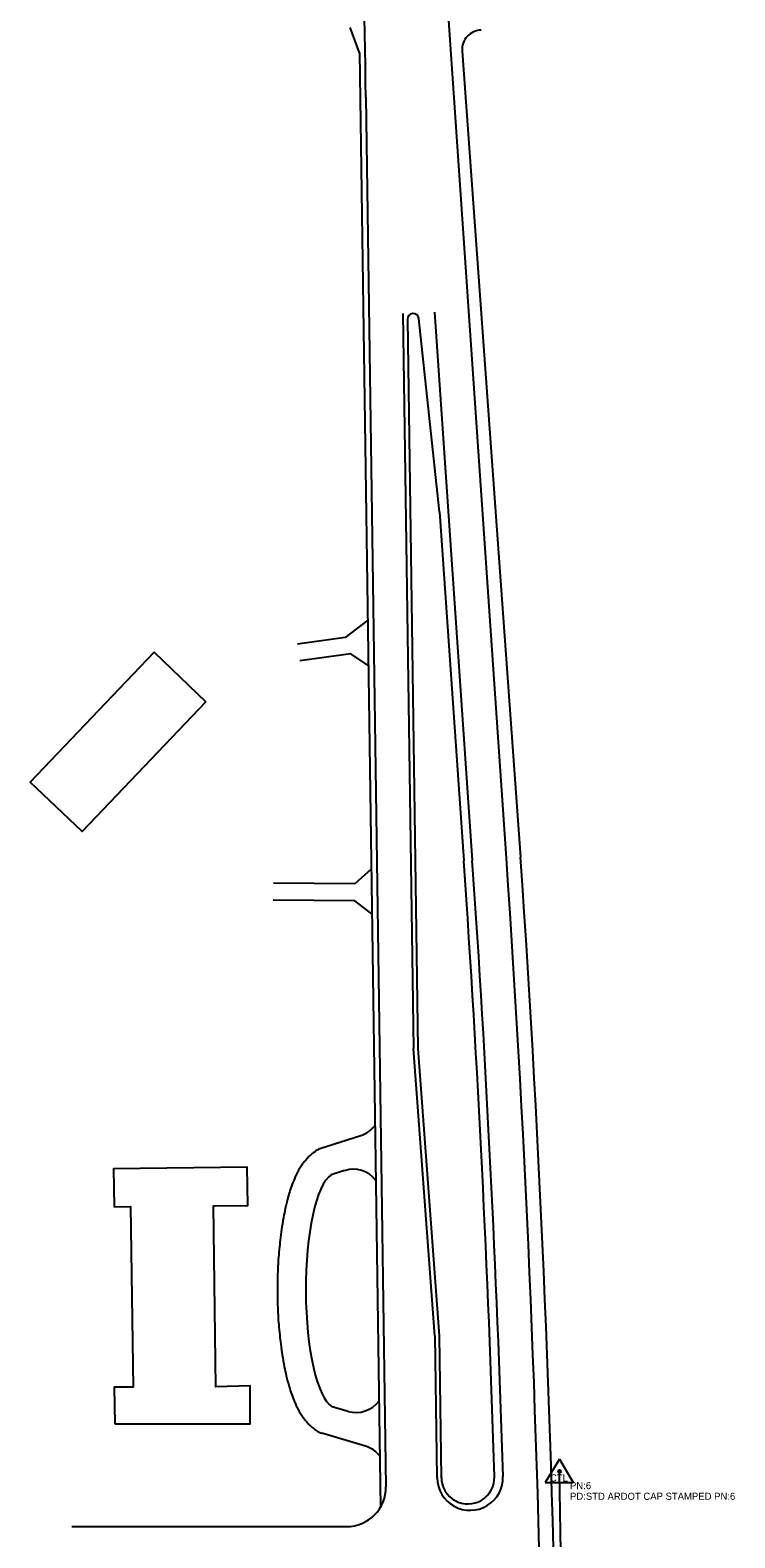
# Model space of a CAD drawing. Extents: x 1676038 to 1677961, y 226475 to 233854.
# Drawn here: x 1677093 to 1677589, y 230414 to 231476 of the extents above; entities that cross this region are included whole.
import ezdxf

# ---------------------------------------------------------------- set-up
doc = ezdxf.new("R2010")
doc.units = 0
for name, color, linetype in [('S_BASELINE', 7, 'Continuous'), ('S_BUILDING', 7, 'Continuous'), ('S_DRIVEWAY', 7, 'Continuous'), ('S_EDGE_PAVEMENT', 7, 'Continuous'), ('S_PRIMARY_CTL', 7, 'Continuous'), ('S_PRIMARY_CTL_ANNOT', 7, 'Continuous'), ('S_SHOULDER', 7, 'Continuous')]:
    doc.layers.add(name, color=color, linetype=linetype)

msp = doc.modelspace()

# ---------------------------------------------------------------- linework, layer by layer
at = {"layer": 'S_BASELINE'}
msp.add_line((1677475.6, 229873.4), (1677466, 230460.5), dxfattribs=at)
at = {"layer": 'S_BUILDING'}
for points in [[(1677217.2, 231002.7), (1677130, 230911.2), (1677093.5, 230946), (1677180.8, 231037.6)], [(1677153.1, 230494.1), (1677248.4, 230494), (1677248.4, 230520.8), (1677224.2, 230520.2), (1677222.5, 230647.6), (1677246.6, 230647.9), (1677246.2, 230674.8), (1677152.2, 230673.6), (1677152.6, 230646.8), (1677164.2, 230647), (1677165.9, 230519.9), (1677152.5, 230519.8)]]:
    msp.add_lwpolyline(points, close=True, dxfattribs=at)
at = {"layer": 'S_DRIVEWAY'}
for p, q in [((1677331.1, 231060.1), (1677315.3, 231048)), ((1677315.3, 231048), (1677281.7, 231043.3)), ((1677319.2, 231036.4), (1677283.3, 231031.4)), ((1677331.5, 231028.1), (1677319.2, 231036.4)), ((1677333.6, 230884.8), (1677322.1, 230874.5)), ((1677322.1, 230874.5), (1677264.7, 230874.8)), ((1677321.9, 230862.5), (1677264.6, 230862.8)), ((1677334.1, 230853), (1677321.9, 230862.5)), ((1677326.2, 230697), (1677297.4, 230687.8)), ((1677314.8, 230672.4), (1677305.3, 230669.3)), ((1677317.2, 230502.8), (1677306, 230506.1)), ((1677329.4, 230478.3), (1677298.7, 230487.4))]:
    msp.add_line(p, q, dxfattribs=at)
for centre, radius, start, end in [((1677411.2, 231462), 13.7, 90.7662, 183.9401), ((1677320.1, 230716.1), 20, 287.8138, 323.9607), ((1677321, 230653.3), 20, 37.7005, 107.8138), ((1677322.9, 230522), 20, 253.613, 323.9607), ((1677323.8, 230459.1), 20, 37.7005, 73.613)]:
    msp.add_arc(centre, radius, start, end, dxfattribs=at)
msp.add_ellipse((1677309.1, 230587.8), major_axis=(-0.2, 82.7), ratio=0.261188, start_param=0.165858, end_param=2.986693, dxfattribs=at)
msp.add_open_spline([(1677297.4, 230687.8), (1677296.9, 230687.5), (1677296.3, 230687.2), (1677294.5, 230686.2), (1677293.5, 230685.5), (1677290.5, 230683.2), (1677288.8, 230681.5), (1677286, 230678.2), (1677284.8, 230676.5), (1677282.6, 230673), (1677281.6, 230671.3), (1677279.9, 230667.6), (1677279.1, 230665.7), (1677276.8, 230659.9), (1677275.5, 230655.7), (1677273.2, 230646.7), (1677272.2, 230641.9), (1677270.5, 230632), (1677269.8, 230626.8), (1677268.1, 230610.7), (1677267.5, 230599.3), (1677267.6, 230576), (1677268.2, 230564.6), (1677270, 230548.5), (1677270.7, 230543.3), (1677272.5, 230533.4), (1677273.5, 230528.6), (1677275.9, 230519.6), (1677277.2, 230515.5), (1677279.5, 230509.6), (1677280.3, 230507.8), (1677282.1, 230504.1), (1677283.1, 230502.4), (1677285.3, 230498.9), (1677286.5, 230497.2), (1677289.4, 230493.9), (1677291, 230492.3), (1677294, 230490), (1677295.1, 230489.3), (1677297.1, 230488.1), (1677297.9, 230487.7), (1677298.7, 230487.4)], degree=3, dxfattribs=at)
at = {"layer": 'S_EDGE_PAVEMENT'}
for p, q in [((1677360, 231888.4), (1677428.6, 230892.5)), ((1677329.7, 231428.4), (1677343.9, 230449.7)), ((1677355.9, 231276), (1677363.4, 230758.3)), ((1677378.1, 231277.1), (1677404.7, 230890.9)), ((1677378.4, 230556.1), (1677363.4, 230758.3)), ((1677378.4, 230556.1), (1677379.8, 230456)), ((1677122.8, 230421.8), (1677316.2, 230421.7))]:
    msp.add_line(p, q, dxfattribs=at)
for centre, radius, start, end in [((1671600.8, 231345.3), 5729.6, 0.83062, 4.42552), ((1665972.6, 230103.5), 11459.2, 1.76792, 3.94011), ((1665972.6, 230103.5), 11483.2, 0.83062, 3.94011), ((1677403.1, 230456.3), 23.2, 180.8306, 1.7679), ((1677316.2, 230449.3), 27.7, 269.9633, 0.8306)]:
    msp.add_arc(centre, radius, start, end, dxfattribs=at)
at = {"layer": 'S_PRIMARY_CTL'}
for p, q in [((1677466, 230469.2), (1677456, 230452.7)), ((1677466, 230469.2), (1677475.8, 230452.7)), ((1677456, 230452.7), (1677475.8, 230452.7))]:
    msp.add_line(p, q, dxfattribs=at)
for radius in [1.04, 0.609, 0.344]:
    msp.add_circle((1677466, 230460.5), radius, dxfattribs=at)
at = {"layer": 'S_SHOULDER'}
for p, q in [((1677325.3, 231459.7), (1677318.8, 231477.6)), ((1677325.3, 231459.7), (1677340.1, 230435.3)), ((1677397.5, 231461), (1677438.6, 230893.2)), ((1677359, 231272), (1677366.4, 230758.4)), ((1677381.7, 231136.3), (1677367, 231272.5)), ((1677381.7, 231136.3), (1677398.7, 230890.5)), ((1677366.4, 230758.4), (1677381.4, 230556.1)), ((1677381.4, 230556.1), (1677382.8, 230456))]:
    msp.add_line(p, q, dxfattribs=at)
for centre, radius, start, end in [((1677363, 231272.1), 4, 6.1859, 180.8306), ((1665972.6, 230103.5), 11453.2, 1.76792, 3.94011), ((1665972.6, 230103.5), 11493.2, 0.83062, 3.94011), ((1677401.6, 230456.3), 18.7, 180.7931, 1.7304)]:
    msp.add_arc(centre, radius, start, end, dxfattribs=at)

# ---------------------------------------------------------------- texts
at = {"layer": 'S_PRIMARY_CTL'}
msp.add_text('CTL', height=5, rotation=360, dxfattribs=at).set_placement((1677459.4, 230453.4))
at = {"layer": 'S_PRIMARY_CTL_ANNOT'}
for s, p in [('PN:6', (1677473.5, 230448)), ('PD:STD ARDOT CAP STAMPED PN:6', (1677473.5, 230440.5))]:
    msp.add_text(s, height=5, dxfattribs=at).set_placement(p)

doc.saveas('drawing.dxf')
